// Mitsubishi GX Works2 project: MM-12MT-4MT-FE280-FX-A例程   PLC: FX1S

PROGRAM MAIN
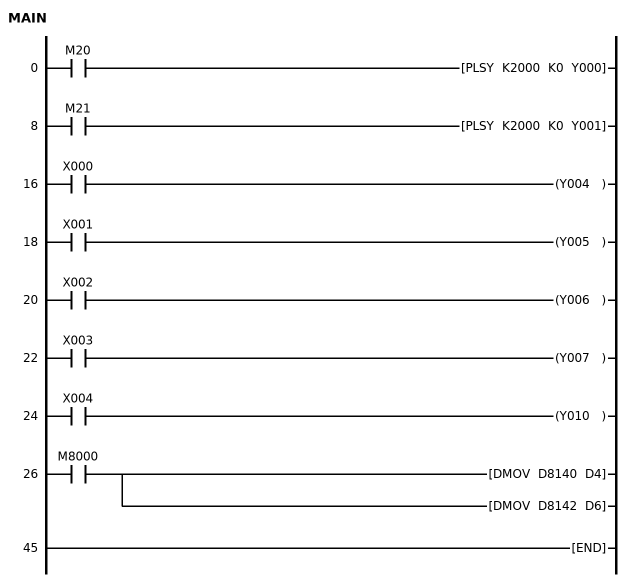
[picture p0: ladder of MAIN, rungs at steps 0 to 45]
0     LD      M20
      PLSY    K2000 K0 Y000
8     LD      M21
      PLSY    K2000 K0 Y001
16    LD      X000
      OUT     Y004
18    LD      X001
      OUT     Y005
20    LD      X002
      OUT     Y006
22    LD      X003
      OUT     Y007
24    LD      X004
      OUT     Y010
26    LD      M8000
      DMOV    D8140 D4
      DMOV    D8142 D6
45    END
END_PROGRAM
